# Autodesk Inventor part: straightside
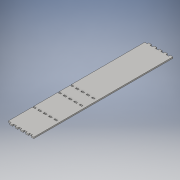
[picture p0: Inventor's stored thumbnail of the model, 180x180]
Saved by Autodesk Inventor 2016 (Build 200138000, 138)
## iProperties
Created: 2017-03
Part Number: straightside
Material: Generic
Document SubType Name: Modeling
Designer: Corey
Density: 1 g/cm^3
Appearance: Default
Author: Corey
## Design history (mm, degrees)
sketch "Sketch1"
  geometry: L1 (0, 0)-(368.3, 0); L2 (368.3, 0)-(368.3, -1917.7); L3 (368.3, -1917.7)-(0, -1917.7); L4 (0, -1917.7)-(0, 0)
  constraints: 8 end point, 2 parallel, 1 horizontal, 1 perpendicular
  dimensions: "d0" = 368.3 distance of L2.end L3.end (= panel); "d1" = 1917.7 distance of L1.end L2.end (= height)
extrude "body" new body sketch "Sketch1" distance "d2" = 18.034 (= thick); taper "d3" = 0 deg
sketch "Sketch2"
  geometry: L1 (-368.3, 0)-(-331.47, 0); L2 (-331.47, 0)-(-331.47, 18.034); L3 (-331.47, 18.034)-(-368.3, 18.034); L4 (-368.3, 18.034)-(-368.3, 0); L5 (-368.3, 0)-(-331.47, 18.034); L6 (-331.47, 0)-(-368.3, 18.034); L7 (-368.3, 0)-(0, 0) reference; L8 (-368.3, 1917.7)-(-368.3, 0) reference; L9 (-368.3, 348.234)-(-331.47, 348.234); L10 (-331.47, 348.234)-(-331.47, 366.268); L11 (-331.47, 366.268)-(-368.3, 366.268); L12 (-368.3, 366.268)-(-368.3, 348.234); L13 (-368.3, 348.234)-(-331.47, 366.268); L14 (-331.47, 348.234)-(-368.3, 366.268); L15 (-368.3, 696.468)-(-331.47, 696.468); L16 (-331.47, 696.468)-(-331.47, 714.502); L17 (-331.47, 714.502)-(-368.3, 714.502); L18 (-368.3, 714.502)-(-368.3, 696.468); L19 (-368.3, 696.468)-(-331.47, 714.502); L20 (-331.47, 696.468)-(-368.3, 714.502); L21 (-368.3, 866.902)-(-331.47, 866.902); L22 (-331.47, 866.902)-(-331.47, 884.936); L23 (-368.3, 866.902)-(-331.47, 884.936); L24 (-331.47, 884.936)-(-368.3, 884.936); L25 (-368.3, 884.936)-(-368.3, 866.902); L26 (-331.47, 866.902)-(-368.3, 884.936); 4 further points
  constraints: 48 end point, 8 midpoint, 8 parallel, 5 collinear, 4 horizontal, 4 perpendicular
  dimensions: "d4" = 36.83 distance of L3.end L2.end (= 0.1 x panel); "d5" = 18.034 distance of L2.end L1.end (= thick); "d6" = 36.83 distance of L11.end L10.end (= d4); "d7" = 18.034 distance of L10.end L9.end (= d5); "d8" = 348.234 distance of point (-349.885, 9.017) point (-349.885, 357.251) (= sweater + thick); "d9" = 36.83 distance of L17.end L16.end (= d11); "d10" = 18.034 distance of L16.end L15.end (= d5); "d15" = 348.234 distance of point (-349.885, 357.251) point (-349.885, 705.485) (= sweater + thick); "d16" = 36.83 distance of L24.end L22.end (= d18); "d17" = 18.034 distance of L22.end L21.end (= d5); "d22" = 170.434 distance of point (-349.885, 705.485) point (-349.885, 875.919) (= shoe + thick)
extrude "Extrusion2" cut sketch "Sketch2" stored distance "d23" = 18.034 (= thick); taper "d24" = 0 deg
pattern_linear "Rectangular Pattern1" dims "d27" = 73.66 (= 0.2 x panel)
sketch "Sketch3"
  geometry: L1 (-368.3, 884.936)-(-368.3, 1917.7) reference; L2 (-368.3, 1917.7)-(-331.47, 1917.7); L3 (-331.47, 1917.7)-(-331.47, 1896.491); L4 (-331.47, 1896.491)-(-368.3, 1896.491); L5 (-368.3, 1896.491)-(-368.3, 1917.7); 1 further point
  constraints: 8 end point, 2 parallel, 1 horizontal, 1 perpendicular
  dimensions: "d28" = 36.83 distance of L3.end L4.end (= 0.1 x panel); "d29" = 21.209 distance of L2.end L3.end (= thick + 0.5 x bit)
extrude "Extrusion3" cut sketch "Sketch3" stored distance "d30" = 25.4; taper "d31" = 0 deg
pattern_linear "Rectangular Pattern2" dims "d34" = 73.66 (= 0.2 x panel)
body "Solid1"
other parameters: "thick" = 18.034 [user parameter; used in 7 equation terms], "top" = 152.4 [user parameter], "bit" = 6.35 [user parameter; used in 1 equation term], "depth" = 425.45 [user parameter], "height" = 1917.7 [user parameter; used in 1 equation term], "width" = 1117.6 [user parameter], "panel" = 368.3 [user parameter; used in 5 equation terms], "shoe" = 152.4 [user parameter; used in 1 equation term], "sweater" = 330.2 [user parameter; used in 2 equation terms], "d11" = 36.83 (= 0.1 x d14), "d12" = 19.05 (= d13), "d13" = 19.05 [user parameter; used in 1 equation term], "d14" = 368.3 [user parameter; used in 1 equation term], "d18" = 36.83 (= 0.1 x d21), "d19" = 19.05 (= d20), "d20" = 19.05 [user parameter; used in 1 equation term], "d21" = 368.3 [user parameter; used in 1 equation term], "osb" = 19.05 [user parameter]
